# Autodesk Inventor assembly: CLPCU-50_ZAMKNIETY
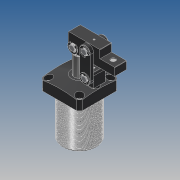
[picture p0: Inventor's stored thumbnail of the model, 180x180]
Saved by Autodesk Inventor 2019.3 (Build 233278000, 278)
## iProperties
Created: 2010-03
Part Number: CLPCU-50_ZAMKNIETY
Material: Ogólny
Document SubType Name: Assembly
Designer: CADENGINEERING4
Sending System: PRO/ENGINEER BY PARAMETRIC TECHNOLOGY CORPORATION, 2007170
Preprocessor: PRO/ENGINEER BY PARAMETRIC TECHNOLOGY CORPORATION, 2007170
Title: CPLCU-50_ASM
Author: Administrator
Revision Number: 2LAST_VERSION
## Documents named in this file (10)
- E:\SERWER_ZAPAS\MODELE brakujace\PNEUMATIC\CPLCU(STEP)\cplcu-50_asm\CLPCU-50_ZAMKNIETY.iam
- E:\SERWER_ZAPAS\MODELE brakujace\PNEUMATIC\CPLCU(STEP)\cplcu-50_asm\CPLCU-50-07.ipt
- E:\SERWER_ZAPAS\MODELE brakujace\PNEUMATIC\CPLCU(STEP)\cplcu-50_asm\CPLCU-50-05.ipt
- E:\SERWER_ZAPAS\MODELE brakujace\PNEUMATIC\CPLCU(STEP)\cplcu-50_asm\CPLCU-50-06.ipt
- E:\SERWER_ZAPAS\MODELE brakujace\PNEUMATIC\CPLCU(STEP)\cplcu-50_asm\CPLCU-50-01.ipt
- E:\SERWER_ZAPAS\MODELE brakujace\PNEUMATIC\CPLCU(STEP)\cplcu-50_asm\CPLCU-50-02.ipt
- E:\SERWER_ZAPAS\MODELE brakujace\PNEUMATIC\CPLCU(STEP)\cplcu-50_asm\CPLCU-50-08.ipt
- E:\SERWER_ZAPAS\MODELE brakujace\PNEUMATIC\CPLCU(STEP)\cplcu-50_asm\CPLCU-50-03.ipt
- E:\SERWER_ZAPAS\MODELE brakujace\PNEUMATIC\CPLCU(STEP)\cplcu-50_asm\CPLCU-50-04.ipt
- E:\SERWER_ZAPAS\MODELE brakujace\PNEUMATIC\CPLCU(STEP)\cplcu-50_asm\CPLCU-50-09.ipt
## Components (21 placed, 21 different names)
1. CPLCU-50-07_0 — Zestawiające:25
2. CPLCU-50-05_1 — Zestawiające:1, Zestawiające:2, Kątowe:1
3. CPLCU-50-06_2 — Zestawiające:15, Zestawiające:16, Zestawiające:17, Zestawiające:18, Zestawiające:22, Zestawiające:25
4. CPLCU-50-01_3 — Zestawiające:21, Zestawiające:22, Zestawiające:23, Zestawiające:24, Kątowe:1
5. CPLCU-50-02_4 — Zestawiające:1, Zestawiające:3, Zestawiające:4, Zestawiające:10
6. CPLCU-50-02_5 — Zestawiające:2, Zestawiające:3, Zestawiające:4, Zestawiające:5, Zestawiające:24
7. CPLCU-50-08_6 — Zestawiające:15, Zestawiające:17
8. CPLCU-50-08_7 — Zestawiające:6, Zestawiające:9
9. CPLCU-50-08_8
10. CPLCU-50-08_9 — Zestawiające:16, Zestawiające:18, Zestawiające:19, Zestawiające:20, Zestawiające:21
11. CPLCU-50-08_10 — Zestawiające:5
12. CPLCU-50-08_11 — Zestawiające:7, Zestawiające:8
13. CPLCU-50-03_12 — Równoległe:5, Równoległe:6, Zestawiające:13, Zestawiające:14, Zestawiające:19
14. CPLCU-50-04_13 — Równoległe:1, Równoległe:4, Zestawiające:6, Zestawiające:7, Zestawiające:10, Zestawiające:11, Zestawiające:12, Zestawiające:23
15. CPLCU-50-04_14 — Równoległe:1, Równoległe:4
16. CPLCU-50-09_15 — Równoległe:6, Zestawiające:13
17. CPLCU-50-09_16 — Równoległe:5, Zestawiające:14, Zestawiające:20
18. CPLCU-50-09_17 — Równoległe:3, Zestawiające:9, Zestawiające:11
19. CPLCU-50-09_18 — Równoległe:2, Zestawiające:8, Zestawiające:12
20. CPLCU-50-09_19 — Równoległe:3
21. CPLCU-50-09_20 — Równoległe:2
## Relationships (32: Mate 25, Flush 6, Angle 1)
- Równoległe:1 [Flush]: CPLCU-50-04_13 ↔ CPLCU-50-04_14
- Równoległe:2 [Flush]: CPLCU-50-09_18 ↔ CPLCU-50-09_20
- Równoległe:3 [Flush]: CPLCU-50-09_17 ↔ CPLCU-50-09_19
- Równoległe:4 [Flush]: CPLCU-50-04_13 ↔ CPLCU-50-04_14
- Zestawiające:1 [Mate]: CPLCU-50-05_1 ↔ CPLCU-50-02_4
- Zestawiające:2 [Mate]: CPLCU-50-05_1 ↔ CPLCU-50-02_5
- Zestawiające:3 [Mate]: CPLCU-50-02_4 ↔ CPLCU-50-02_5
- Zestawiające:4 [Mate]: CPLCU-50-02_4 ↔ CPLCU-50-02_5
- Zestawiające:5 [Mate]: CPLCU-50-02_5 ↔ CPLCU-50-08_10
- Zestawiające:6 [Mate]: CPLCU-50-08_7 ↔ CPLCU-50-04_13
- Zestawiające:7 [Mate]: CPLCU-50-08_11 ↔ CPLCU-50-04_13
- Zestawiające:8 [Mate]: CPLCU-50-08_11 ↔ CPLCU-50-09_18
- Zestawiające:9 [Mate]: CPLCU-50-08_7 ↔ CPLCU-50-09_17
- Zestawiające:10 [Mate]: CPLCU-50-02_4 ↔ CPLCU-50-04_13
- Zestawiające:11 [Mate]: CPLCU-50-04_13 ↔ CPLCU-50-09_17
- Zestawiające:12 [Mate]: CPLCU-50-04_13 ↔ CPLCU-50-09_18
- Równoległe:5 [Flush]: CPLCU-50-03_12 ↔ CPLCU-50-09_16
- Równoległe:6 [Flush]: CPLCU-50-03_12 ↔ CPLCU-50-09_15
- Zestawiające:13 [Mate]: CPLCU-50-03_12 ↔ CPLCU-50-09_15
- Zestawiające:14 [Mate]: CPLCU-50-03_12 ↔ CPLCU-50-09_16
- Zestawiające:15 [Mate]: CPLCU-50-06_2 ↔ CPLCU-50-08_6
- Zestawiające:16 [Mate]: CPLCU-50-06_2 ↔ CPLCU-50-08_9
- Zestawiające:17 [Mate]: CPLCU-50-06_2 ↔ CPLCU-50-08_6
- Zestawiające:18 [Mate]: CPLCU-50-06_2 ↔ CPLCU-50-08_9
- Zestawiające:19 [Mate]: CPLCU-50-08_9 ↔ CPLCU-50-03_12
- Zestawiające:20 [Mate]: CPLCU-50-08_9 ↔ CPLCU-50-09_16
- Zestawiające:21 [Mate]: CPLCU-50-01_3 ↔ CPLCU-50-08_9
- Zestawiające:22 [Mate]: CPLCU-50-06_2 ↔ CPLCU-50-01_3
- Zestawiające:23 [Mate]: CPLCU-50-01_3 ↔ CPLCU-50-04_13
- Zestawiające:24 [Mate]: CPLCU-50-01_3 ↔ CPLCU-50-02_5
- Zestawiające:25 [Mate]: CPLCU-50-07_0 ↔ CPLCU-50-06_2
- Kątowe:1 [Angle]: CPLCU-50-05_1 ↔ CPLCU-50-01_3
